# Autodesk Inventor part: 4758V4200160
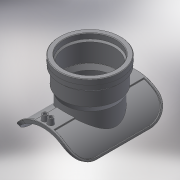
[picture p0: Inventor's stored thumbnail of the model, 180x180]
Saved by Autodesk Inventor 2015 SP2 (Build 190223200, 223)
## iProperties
Created: 2017-08
Part Number: 4758V4200160
Material: Generic
Description: PLASSON WASTEWATER SADDLE 200X160 PVC/PP ADAPTOR INLET
Document SubType Name: Modeling
Designer: Кирилл
Density: 1 g/cm^3
Appearance: Default
Author: Кирилл
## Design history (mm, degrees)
derived "4758V4.ipt"
feature "Solid1::4758V4.ipt"
feature "Solid2::4758V4.ipt"
feature "Solid3::4758V4.ipt"
tag "TaggingFeature1"
body "Solid1"
other parameters: "d1" = 208, "d4" = 0, "d5" = 62.4, "d6" = 6.4, "d7" = 30 deg, "d8" = 15 deg, "d10" = 0, "d38" = 1, "d40" = 126, "d41" = 15, "d42" = 130.5, "d43" = 17.6, "d44" = 8.8, "d46" = 5 deg, "d47" = 4, "d49" = 4, "d51" = 14, "d52" = 0, "d53" = 3, "d54" = 0, "d57" = 0.5, "d59" = 16, "d60" = 5.6, "d61" = 40 deg, "d62" = 152, "d63" = 156.8, "d64" = 144, "d65" = 155 deg, "d66" = 125, "d68" = 188.1, "d69" = 45 deg, "d70" = 175, "d72" = 7.5, "d75" = 0, "d77" = 0, "d78" = 1.6, "d81" = 37.5, "B_" = 208, "H_" = 125, "d71" = 7.5
